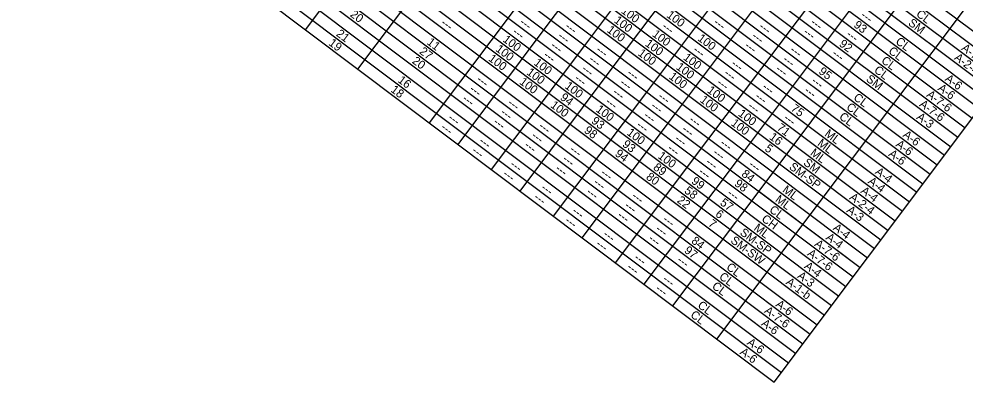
# Model space of a CAD drawing. Extents: x 627484.2 to 627514.4, y 367972.1 to 367996.9.
# Drawn here: x 627490.82 to 627497, y 367985.28 to 367987.65 of the extents above; entities that cross this region are included whole.
import ezdxf

# ---------------------------------------------------------------- set-up
doc = ezdxf.new("R2010")
doc.units = 0
doc.layers.add('Default', color=7, linetype='Continuous')

msp = doc.modelspace()

# ---------------------------------------------------------------- linework, layer by layer
at = {"layer": 'Default'}
for p, q in [((627492.0824, 367991.303), (627497.3218, 367987.3687)), ((627492.0355, 367991.2406), (627497.2749, 367987.3063)), ((627491.9887, 367991.1783), (627497.2281, 367987.244)), ((627491.9419, 367991.1159), (627497.1813, 367987.1816)), ((627491.9009, 367991.0613), (627497.1403, 367987.127)), ((627491.854, 367990.999), (627497.0935, 367987.0646)), ((627491.8072, 367990.9366), (627497.0466, 367987.0023)), ((627491.7604, 367990.8742), (627496.9998, 367986.9399)), ((627491.7135, 367990.8118), (627496.9529, 367986.8775)), ((627491.6667, 367990.7495), (627496.9061, 367986.8151)), ((627491.6257, 367990.6949), (627496.8651, 367986.7606)), ((627491.5789, 367990.6325), (627496.8183, 367986.6982)), ((627491.532, 367990.5701), (627496.7715, 367986.6358)), ((627491.4852, 367990.5078), (627496.7246, 367986.5734)), ((627491.4442, 367990.4532), (627496.6836, 367986.5189)), ((627491.3974, 367990.3908), (627496.6368, 367986.4565)), ((627491.3506, 367990.3284), (627496.59, 367986.3941)), ((627491.3037, 367990.2661), (627496.5431, 367986.3317)), ((627491.2569, 367990.2037), (627496.4963, 367986.2694)), ((627491.21, 367990.1413), (627496.4495, 367986.207)), ((627494.2955, 367987.6415), (627496.1778, 367990.1481)), ((627491.1691, 367990.0868), (627496.4085, 367986.1524)), ((627491.1222, 367990.0244), (627496.3616, 367986.0901)), ((627494.5138, 367987.4776), (627496.3961, 367989.9842)), ((627491.0754, 367989.962), (627496.3148, 367986.0277)), ((627491.0286, 367989.8996), (627496.268, 367985.9653)), ((627490.9817, 367989.8373), (627496.2211, 367985.9029)), ((627494.701, 367987.3371), (627496.5832, 367989.8437)), ((627490.9349, 367989.7749), (627496.1743, 367985.8406)), ((627490.888, 367989.7125), (627496.1275, 367985.7782)), ((627494.9193, 367987.1731), (627496.8015, 367989.6798)), ((627490.8412, 367989.6501), (627496.0806, 367985.7158)), ((627490.7944, 367989.5878), (627496.0338, 367985.6534)), ((627495.1064, 367987.0326), (627496.9886, 367989.5392)), ((627490.7475, 367989.5254), (627495.9869, 367985.5911)), ((627490.7007, 367989.463), (627495.9401, 367985.5287)), ((627490.6539, 367989.4007), (627495.8933, 367985.4663)), ((627495.3247, 367986.8687), (627497.2069, 367989.3753)), ((627490.607, 367989.3383), (627495.8464, 367985.404)), ((627490.5602, 367989.2759), (627495.7996, 367985.3416)), ((627495.5118, 367986.7282), (627497.394, 367989.2348)), ((627495.6989, 367986.5877), (627497.6865, 367989.2346)), ((627490.5134, 367989.2135), (627495.7528, 367985.2792)), ((627495.9874, 367986.3711), (627497.975, 367989.018)), ((627496.3616, 367986.0901), (627498.3493, 367988.737)), ((627492.6887, 367987.58), (627493.2976, 367988.3909)), ((627493.0318, 367987.3224), (627493.6406, 367988.1333)), ((627493.4995, 367986.9712), (627494.1084, 367987.782)), ((627493.6867, 367986.8307), (627494.2955, 367987.6415)), ((627493.905, 367986.6667), (627494.5138, 367987.4776)), ((627494.0921, 367986.5262), (627494.701, 367987.3371)), ((627494.3104, 367986.3623), (627494.9193, 367987.1731)), ((627494.4975, 367986.2218), (627495.1064, 367987.0326)), ((627494.7158, 367986.0579), (627495.3247, 367986.8687)), ((627494.9029, 367985.9174), (627495.5118, 367986.7282)), ((627495.0901, 367985.7768), (627495.6989, 367986.5877)), ((627495.6521, 367986.5253), (627496.3148, 367986.0277)), ((627495.3785, 367985.5602), (627495.9874, 367986.3711)), ((627495.7528, 367985.2792), (627496.3616, 367986.0901))]:
    msp.add_line(p, q, dxfattribs=at)

# ---------------------------------------------------------------- texts
for s, p in [('20', (627492.9763, 367987.6711)), ('100', (627494.7482, 367987.6939)), ('100', (627495.0446, 367987.6665)), ('---', (627496.3129, 367987.6651)), ('CL', (627496.6757, 367987.6731)), ('---', (627493.5692, 367987.616)), ('---', (627494.084, 367987.6196)), ('100', (627494.7014, 367987.6316)), ('---', (627495.3515, 367987.6189)), ('---', (627495.9853, 367987.6185)), ('93', (627496.2675, 367987.6017)), ('SM', (627496.6235, 367987.6148)), ('21', (627492.8855, 367987.5442)), ('---', (627494.0372, 367987.5573)), ('---', (627494.3804, 367987.5922)), ('100', (627494.6545, 367987.5692)), ('100', (627494.9509, 367987.5417)), ('---', (627495.0142, 367987.5918)), ('---', (627495.6479, 367987.5914)), ('---', (627495.9385, 367987.5561)), ('19', (627492.836, 367987.4838)), ('11', (627493.4782, 367987.4893)), ('100', (627493.974, 367987.5072)), ('---', (627494.3336, 367987.5298)), ('100', (627494.9041, 367987.4794)), ('100', (627495.2473, 367987.5143)), ('---', (627495.6011, 367987.529)), ('92', (627496.1724, 367987.478)), ('---', (627496.2192, 367987.5404)), ('CL', (627496.5411, 367987.4938)), ('27', (627493.4289, 367987.4288)), ('100', (627493.9271, 367987.4448)), ('---', (627494.2867, 367987.4674)), ('---', (627494.5831, 367987.4399)), ('100', (627494.8573, 367987.417)), ('---', (627495.2169, 367987.4396)), ('---', (627495.5542, 367987.4667)), ('---', (627495.8506, 367987.4392)), ('CL', (627496.4942, 367987.4314)), ('A-7-6', (627496.9716, 367987.451)), ('20', (627493.3817, 367987.3666)), ('100', (627493.8803, 367987.3825)), ('100', (627494.1767, 367987.355)), ('---', (627494.2399, 367987.405)), ('---', (627494.5363, 367987.3776)), ('100', (627495.1536, 367987.3895)), ('---', (627495.8038, 367987.3768)), ('---', (627496.1256, 367987.4156)), ('CL', (627496.4474, 367987.369)), ('A-2-4', (627496.9246, 367987.3887)), ('100', (627494.1298, 367987.2926)), ('---', (627494.4895, 367987.3152)), ('100', (627495.1068, 367987.3271)), ('---', (627495.4664, 367987.3497)), ('---', (627495.757, 367987.3144)), ('95', (627496.0386, 367987.2981)), ('CL', (627496.4006, 367987.3067)), ('16', (627493.2881, 367987.2418)), ('---', (627493.803, 367987.2454)), ('100', (627494.083, 367987.2302)), ('---', (627494.4426, 367987.2528)), ('---', (627494.7858, 367987.2877)), ('100', (627495.06, 367987.2648)), ('---', (627495.4196, 367987.2873)), ('---', (627495.9909, 367987.2363)), ('SM', (627496.3483, 367987.2484)), ('A-6', (627496.864, 367987.2513)), ('18', (627493.2419, 367987.179)), ('---', (627493.7562, 367987.183)), ('100', (627494.3794, 367987.2028)), ('---', (627494.739, 367987.2253)), ('100', (627495.3095, 367987.1749)), ('---', (627495.3728, 367987.225)), ('---', (627495.6691, 367987.1975)), ('---', (627495.9441, 367987.1739)), ('A-6', (627496.8171, 367987.189)), ('---', (627493.7093, 367987.1206)), ('94', (627494.3488, 367987.1282)), ('---', (627494.6922, 367987.163)), ('---', (627494.9886, 367987.1355)), ('100', (627495.2627, 367987.1125)), ('---', (627495.6223, 367987.1351)), ('CL', (627496.2659, 367987.1274)), ('A-7-6', (627496.7432, 367987.1469)), ('---', (627494.0057, 367987.0932)), ('100', (627494.2857, 367987.078)), ('100', (627494.5821, 367987.0505)), ('---', (627494.6453, 367987.1006)), ('---', (627494.9417, 367987.0731)), ('---', (627495.5755, 367987.0728)), ('75', (627495.8571, 367987.0564)), ('CL', (627496.2191, 367987.065)), ('A-7-6', (627496.6964, 367987.0845)), ('---', (627493.6157, 367986.9959)), ('---', (627493.9589, 367987.0308)), ('93', (627494.5531, 367986.9748)), ('---', (627494.8949, 367987.0108)), ('100', (627495.5122, 367987.0227)), ('---', (627495.8094, 367986.9946)), ('CL', (627496.1722, 367987.0026)), ('A-3', (627496.6781, 367987.0007)), ('---', (627493.5688, 367986.9335)), ('---', (627493.9121, 367986.9684)), ('---', (627494.2084, 367986.941)), ('98', (627494.5054, 367986.9131)), ('---', (627494.848, 367986.9484)), ('---', (627495.1913, 367986.9833)), ('100', (627495.4654, 367986.9603)), ('71', (627495.7653, 367986.9302)), ('---', (627494.1616, 367986.8786)), ('100', (627494.7848, 367986.8983)), ('---', (627495.1444, 367986.9209)), ('16', (627495.7157, 367986.8699)), ('ML', (627496.0772, 367986.8911)), ('A-6', (627496.5888, 367986.8849)), ('---', (627493.8184, 367986.8437)), ('---', (627494.1148, 367986.8162)), ('93', (627494.7558, 367986.8226)), ('---', (627495.0976, 367986.8585)), ('---', (627495.394, 367986.8311)), ('5', (627495.686, 367986.7947)), ('ML', (627496.0304, 367986.8287)), ('A-6', (627496.542, 367986.8225)), ('---', (627493.7715, 367986.7813)), ('---', (627494.4112, 367986.7887)), ('94', (627494.7073, 367986.7614)), ('100', (627494.9875, 367986.7461)), ('---', (627495.0508, 367986.7962)), ('---', (627495.3471, 367986.7687)), ('ML', (627495.9835, 367986.7663)), ('A-6', (627496.4951, 367986.7601)), ('---', (627494.0211, 367986.6915)), ('---', (627494.3643, 367986.7264)), ('89', (627494.9572, 367986.6714)), ('---', (627495.3003, 367986.7063)), ('---', (627495.5811, 367986.6906)), ('SM-SP', (627495.8452, 367986.6752)), ('SM', (627495.9385, 367986.7026)), ('---', (627493.9743, 367986.6291)), ('---', (627494.3175, 367986.664)), ('---', (627494.6139, 367986.6365)), ('80', (627494.9101, 367986.6092)), ('---', (627495.2535, 367986.6439)), ('84', (627495.5341, 367986.6283)), ('A-4', (627496.4072, 367986.6433)), ('---', (627494.567, 367986.5741)), ('99', (627495.2067, 367986.5815)), ('98', (627495.488, 367986.5654)), ('A-4', (627496.3604, 367986.5809)), ('---', (627494.2238, 367986.5392)), ('---', (627494.5202, 367986.5118)), ('58', (627495.1603, 367986.5188)), ('---', (627495.4406, 367986.5034)), ('ML', (627495.802, 367986.5246)), ('A-2-4', (627496.2396, 367986.4765)), ('A-4', (627496.3135, 367986.5185)), ('---', (627494.177, 367986.4769)), ('---', (627494.8166, 367986.4843)), ('22', (627495.113, 367986.4568)), ('57', (627495.3939, 367986.441)), ('ML', (627495.7552, 367986.4623)), ('---', (627494.4265, 367986.387)), ('---', (627494.7697, 367986.4219)), ('6', (627495.3631, 367986.3665)), ('CL', (627495.7156, 367986.3945)), ('A-3', (627496.2214, 367986.3926)), ('---', (627494.3797, 367986.3247)), ('---', (627494.7229, 367986.3596)), ('---', (627495.0193, 367986.3321)), ('7', (627495.3165, 367986.304)), ('CH', (627495.6651, 367986.3348)), ('---', (627494.9725, 367986.2697)), ('SM-SP', (627495.5232, 367986.2463)), ('ML', (627495.6147, 367986.2751)), ('A-4', (627496.132, 367986.2768)), ('---', (627494.6292, 367986.2348)), ('---', (627494.9256, 367986.2073)), ('84', (627495.2062, 367986.1917)), ('SM-SW', (627495.4628, 367986.1941)), ('A-7-6', (627496.0114, 367986.1723)), ('A-4', (627496.0852, 367986.2145)), ('---', (627494.5824, 367986.1724)), ('97', (627495.1597, 367986.1291)), ('A-7-6', (627495.9646, 367986.11)), ('---', (627494.8319, 367986.0826)), ('---', (627495.1127, 367986.0668)), ('---', (627494.7851, 367986.0202)), ('CL', (627495.4346, 367986.0202)), ('A-4', (627495.9447, 367986.0274)), ('---', (627495.0191, 367985.9421)), ('CL', (627495.3877, 367985.9579)), ('A-1-b', (627495.824, 367985.9229)), ('A-3', (627495.8994, 367985.9638)), ('---', (627494.9722, 367985.8797)), ('CL', (627495.3409, 367985.8955)), ('CL', (627495.2472, 367985.7707)), ('A-7-6', (627495.6836, 367985.7357)), ('A-6', (627495.7575, 367985.7778)), ('CL', (627495.2004, 367985.7084)), ('A-6', (627495.6638, 367985.653)), ('A-6', (627495.5701, 367985.5283)), ('A-6', (627495.5233, 367985.4659))]:
    msp.add_text(s, height=0.055, rotation=323.09678, dxfattribs=at).set_placement(p)

doc.saveas('drawing.dxf')
